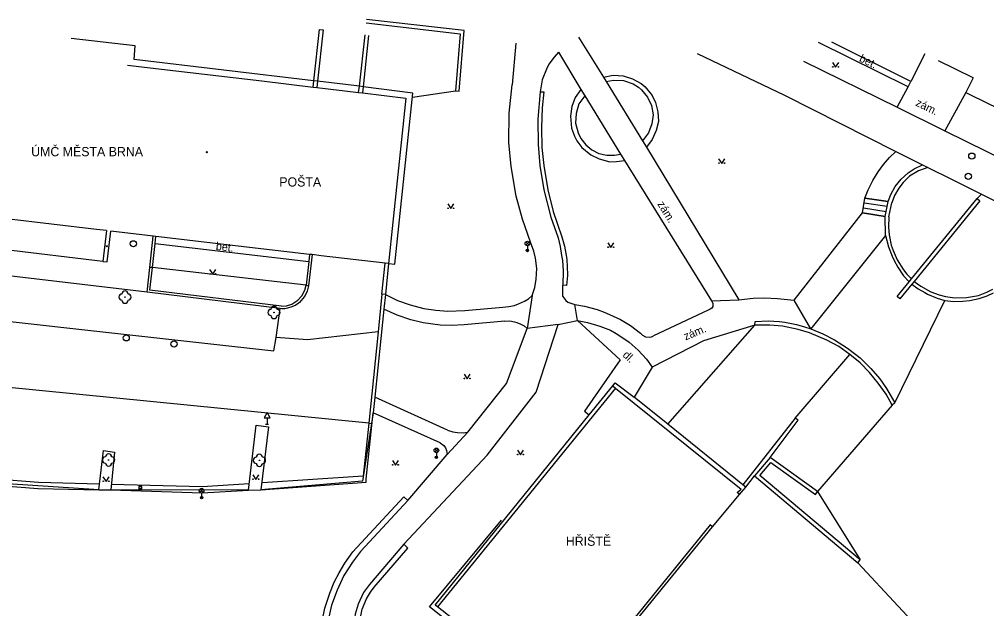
# Model space of a CAD drawing. Extents: x -602419 to -601554, y -1162937 to -1162362.
# Drawn here: x -602331.7 to -602253.1, y -1162453.4 to -1162405.5 of the extents above; entities that cross this region are included whole.
import ezdxf

# ---------------------------------------------------------------- set-up
doc = ezdxf.new("R2010")
doc.units = 0
doc.layers.add('Podklad', color=7, linetype='Continuous')

msp = doc.modelspace()

# ---------------------------------------------------------------- linework, layer by layer
at = {"layer": 'Podklad'}
for p, q in [((-602290.5725, -1162423.83), (-602290.3075, -1162423.565)), ((-602290.5725, -1162423.565), (-602290.3075, -1162423.83)), ((-602290.44, -1162423.885), (-602290.44, -1162424.26)), ((-602311.705, -1162438.36), (-602311.455, -1162438.36)), ((-602311.58, -1162437.851), (-602311.58, -1162438.36)), ((-602297.9625, -1162440.63), (-602297.6975, -1162440.365)), ((-602297.9625, -1162440.365), (-602297.6975, -1162440.63)), ((-602297.83, -1162440.685), (-602297.83, -1162441.06)), ((-602321.995, -1162443.56), (-602321.745, -1162443.56)), ((-602317.0325, -1162443.91), (-602316.7675, -1162443.645)), ((-602317.0325, -1162443.645), (-602316.7675, -1162443.91)), ((-602316.9, -1162443.965), (-602316.9, -1162444.34))]:
    msp.add_line(p, q, dxfattribs=at)
for points in [[(-602295.98, -1162411.33), (-602295.59, -1162406.4), (-602303.5, -1162405.49)], [(-602307.79, -1162410.49), (-602307.32, -1162406.31), (-602307.03, -1162406.35)], [(-602307.03, -1162406.35), (-602307.49, -1162410.52)], [(-602303.53, -1162405.78), (-602295.9099, -1162406.68), (-602296.27, -1162411.3), (-602295.98, -1162411.33)], [(-602307.8, -1162410.49), (-602322.39, -1162408.76), (-602322.3, -1162407.65), (-602327.48, -1162407.04)], [(-602304.09, -1162410.92), (-602303.63, -1162406.76)], [(-602303.34, -1162406.8), (-602303.79, -1162410.96)], [(-602286.3, -1162406.94), (-602284.26, -1162410.18)], [(-602291.38, -1162407.43), (-602291.68, -1162410.8)], [(-602259.53, -1162410.98), (-602266.8, -1162407.36)], [(-602259.3, -1162410.54), (-602265.73, -1162407.34)], [(-602287.9099, -1162408.1599), (-602288.26, -1162408.56), (-602288.7, -1162409.13), (-602288.9, -1162409.55), (-602289.24, -1162410.4), (-602289.4099, -1162411.39)], [(-602287.9099, -1162408.1599), (-602286.1, -1162411.19)], [(-602276.6599, -1162408.26), (-602269.55, -1162411.6599)], [(-602258.17, -1162408.3), (-602259.3, -1162410.54)], [(-602322.93, -1162409.2), (-602319, -1162409.67)], [(-602268.03, -1162408.89), (-602260.42, -1162412.63)], [(-602265.6599, -1162409.005), (-602265.4099, -1162409.38), (-602265.1599, -1162409.005)], [(-602254.25, -1162410.25), (-602257.06, -1162408.86)], [(-602319, -1162409.67), (-602312.02, -1162410.49)], [(-602284.26, -1162410.18), (-602283.4699, -1162410.03), (-602282.67, -1162410.07), (-602281.9099, -1162410.31), (-602281.2, -1162410.69), (-602280.89, -1162410.9699), (-602280.32, -1162411.67), (-602280.04, -1162412.25), (-602279.84, -1162413), (-602279.8, -1162413.78), (-602279.98, -1162414.53), (-602280.3, -1162415.24), (-602280.78, -1162415.86)], [(-602284.26, -1162410.18), (-602284.04, -1162410.54)], [(-602254.25, -1162410.25), (-602254.84, -1162411.42)], [(-602312.02, -1162410.49), (-602307.85, -1162410.99)], [(-602307.85, -1162410.99), (-602307.79, -1162410.49)], [(-602307.85, -1162410.99), (-602307.55, -1162411.02)], [(-602307.79, -1162410.49), (-602307.8, -1162410.49)], [(-602307.49, -1162410.52), (-602307.79, -1162410.49)], [(-602307.49, -1162410.52), (-602307.55, -1162411.02)], [(-602307.55, -1162411.02), (-602305.27, -1162411.3)], [(-602304.09, -1162410.92), (-602307.49, -1162410.52)], [(-602304.15, -1162411.43), (-602304.09, -1162410.92)], [(-602303.79, -1162410.96), (-602304.09, -1162410.92)], [(-602303.79, -1162410.96), (-602303.84, -1162411.4699)], [(-602301.73, -1162425.32), (-602301.21, -1162425.38), (-602299.74, -1162411.49), (-602303.79, -1162410.96)], [(-602290.05, -1162427.93), (-602289.85, -1162427.26), (-602289.74, -1162426.58), (-602289.68, -1162425.74), (-602289.78, -1162424.9), (-602289.9099, -1162424.32), (-602290.18, -1162423.58), (-602290.85, -1162421.73), (-602291.36, -1162419.84), (-602291.77, -1162417.43), (-602291.94, -1162415.49), (-602291.92, -1162413.11), (-602291.68, -1162410.8)], [(-602284.04, -1162410.54), (-602283.44, -1162410.42), (-602282.63, -1162410.46), (-602281.86, -1162410.7199), (-602281.42, -1162411.01), (-602281.18, -1162411.21), (-602280.7, -1162411.8), (-602280.37, -1162412.48), (-602280.24, -1162413.24), (-602280.35, -1162413.99), (-602280.61, -1162414.7), (-602281.09, -1162415.35)], [(-602284.04, -1162410.54), (-602281.09, -1162415.35)], [(-602260.42, -1162412.63), (-602259.53, -1162410.98)], [(-602259.53, -1162410.98), (-602259.3, -1162410.54)], [(-602305.27, -1162411.3), (-602304.15, -1162411.43)], [(-602304.15, -1162411.43), (-602303.84, -1162411.4699)], [(-602303.84, -1162411.4699), (-602300.32, -1162411.88)], [(-602300.32, -1162411.88), (-602301.73, -1162425.32)], [(-602299.7728, -1162411.7996), (-602296.27, -1162411.3)], [(-602289.4099, -1162411.39), (-602289.59, -1162413.6), (-602289.56, -1162415.6599), (-602289.42, -1162417.35), (-602289.1, -1162419.34), (-602288.53, -1162421.55), (-602287.94, -1162423.23), (-602287.77, -1162423.94), (-602287.6599, -1162424.6599), (-602287.59, -1162425.08), (-602287.53, -1162425.9099), (-602287.56, -1162427.07)], [(-602289.4099, -1162411.39), (-602289.11, -1162411.39)], [(-602289.11, -1162411.39), (-602289.24, -1162412.67), (-602289.3, -1162414.28), (-602289.26, -1162415.9), (-602289.11, -1162417.37), (-602288.79, -1162419.34), (-602288.34, -1162421.1), (-602287.64, -1162423.1599), (-602287.42, -1162423.92), (-602287.27, -1162424.81), (-602287.25, -1162425.04), (-602287.2, -1162425.54), (-602287.19, -1162426.3), (-602287.26, -1162427.1)], [(-602286.1, -1162411.19), (-602286.56, -1162411.83), (-602286.84, -1162412.57), (-602286.95, -1162413.35), (-602286.85, -1162414.33), (-602286.62, -1162414.98), (-602286.42, -1162415.35), (-602286.01, -1162415.89), (-602285.29, -1162416.49), (-602284.62, -1162416.83), (-602283.76, -1162417.05), (-602283.21, -1162417.03), (-602282.56, -1162416.95)], [(-602285.79, -1162411.7), (-602286.26, -1162412.36), (-602286.48, -1162413.13), (-602286.53, -1162413.93), (-602286.32, -1162414.71), (-602286.11, -1162415.1599), (-602285.71, -1162415.67), (-602285.21, -1162416.08), (-602284.63, -1162416.38), (-602284, -1162416.53), (-602283.36, -1162416.53), (-602282.87, -1162416.44)], [(-602286.1, -1162411.19), (-602285.79, -1162411.7)], [(-602285.79, -1162411.7), (-602282.87, -1162416.44)], [(-602269.55, -1162411.6599), (-602260.51, -1162416.2199)], [(-602254.84, -1162411.42), (-602256.53, -1162414.54)], [(-602254.84, -1162411.42), (-602254.45, -1162411.61)], [(-602254.45, -1162411.61), (-602252.12, -1162412.76)], [(-602260.42, -1162412.63), (-602256.53, -1162414.54)], [(-602256.53, -1162414.54), (-602248.07, -1162418.7199)], [(-602281.09, -1162415.35), (-602280.78, -1162415.86)], [(-602282.87, -1162416.44), (-602282.56, -1162416.95)], [(-602280.78, -1162415.86), (-602273.27, -1162428.26)], [(-602263.03, -1162420.01), (-602262.76, -1162419.34), (-602262.39, -1162418.57), (-602261.96, -1162417.87), (-602261.52, -1162417.27), (-602261.03, -1162416.7199), (-602260.51, -1162416.2199)], [(-602260.51, -1162416.2199), (-602258.36, -1162417.3)], [(-602282.56, -1162416.95), (-602275.5, -1162428.36)], [(-602274.9099, -1162416.815), (-602274.6599, -1162417.19), (-602274.4099, -1162416.815)], [(-602261.15, -1162420.29), (-602260.94, -1162419.71), (-602260.58, -1162419.07), (-602260.1, -1162418.4699), (-602259.53, -1162417.96), (-602259.03, -1162417.62), (-602258.36, -1162417.3)], [(-602258.36, -1162417.3), (-602257.9099, -1162417.52)], [(-602257.9099, -1162417.52), (-602258.69, -1162417.8), (-602259.4, -1162418.23), (-602259.93, -1162418.75), (-602260.29, -1162419.19), (-602260.63, -1162419.8), (-602260.86, -1162420.4)], [(-602257.9099, -1162417.52), (-602255.95, -1162418.51)], [(-602255.95, -1162418.51), (-602248.1599, -1162422.39)], [(-602253.92, -1162420.05), (-602253.5722, -1162419.6943)], [(-602296.9099, -1162420.485), (-602296.6599, -1162420.86), (-602296.4099, -1162420.485)], [(-602268.78, -1162428.31), (-602263.2199, -1162421.21), (-602263.03, -1162420.01)], [(-602261.23, -1162420.69), (-602263.09, -1162420.4099)], [(-602261.15, -1162420.29), (-602263.03, -1162420.01)], [(-602263.03, -1162420.01), (-602261.15, -1162420.29)], [(-602261.35, -1162423.06), (-602261.38, -1162421.49), (-602261.15, -1162420.29)], [(-602261.08, -1162421.52), (-602260.86, -1162420.4)], [(-602259.24, -1162426.57), (-602253.92, -1162420.05)], [(-602253.69, -1162420.24), (-602259.03, -1162426.77)], [(-602253.92, -1162420.05), (-602253.69, -1162420.24)], [(-602263.2199, -1162421.21), (-602261.38, -1162421.49)], [(-602261.38, -1162421.49), (-602263.2199, -1162421.21)], [(-602263.1599, -1162420.81), (-602261.31, -1162421.09)], [(-602325.43, -1162422.56), (-602332.74, -1162421.69)], [(-602261.08, -1162421.52), (-602261.11, -1162422.36), (-602261.06, -1162422.98), (-602260.89, -1162423.83), (-602260.75, -1162424.26), (-602260.42, -1162425.01), (-602259.9099, -1162425.83), (-602259.63, -1162426.18), (-602259.24, -1162426.57)], [(-602324.63, -1162422.65), (-602325.43, -1162422.56)], [(-602324.63, -1162422.65), (-602324.93, -1162425.15)], [(-602324.56, -1162425.19), (-602324.26, -1162422.7)], [(-602320.84, -1162423.09), (-602324.26, -1162422.7)], [(-602382.68, -1162423.5199), (-602382.868, -1162424.418), (-602311.04, -1162432.4129), (-602310.854, -1162431.328)], [(-602310.39, -1162429), (-602310.52, -1162428.98), (-602321.32, -1162427.65), (-602321.11, -1162425.65), (-602320.84, -1162423.09)], [(-602320.62, -1162423.12), (-602320.84, -1162423.09)], [(-602320.68, -1162423.69), (-602320.62, -1162423.12)], [(-602313.93, -1162423.9), (-602320.62, -1162423.12)], [(-602283.9099, -1162423.645), (-602283.6599, -1162424.02), (-602283.4099, -1162423.645)], [(-602261.35, -1162423.06), (-602267.42, -1162430.64)], [(-602261.35, -1162423.06), (-602261.12, -1162423.98), (-602260.83, -1162424.73), (-602260.6599, -1162425.07), (-602260.37, -1162425.61), (-602259.89, -1162426.32), (-602259.45, -1162426.82)], [(-602324.93, -1162425.15), (-602333.02, -1162424.18)], [(-602321.1, -1162427.48), (-602320.9, -1162425.65), (-602320.68, -1162423.69)], [(-602320.68, -1162423.69), (-602308.2, -1162425.15)], [(-602308.13, -1162424.58), (-602313.93, -1162423.9)], [(-602324.93, -1162425.15), (-602324.56, -1162425.19)], [(-602308.2, -1162425.15), (-602308.42, -1162427.08)], [(-602307.93, -1162424.6), (-602308.23, -1162427.14)], [(-602308.13, -1162424.58), (-602308.2, -1162425.15)], [(-602307.93, -1162424.6), (-602308.13, -1162424.58)], [(-602307.19, -1162424.69), (-602307.93, -1162424.6)], [(-602302, -1162425.29), (-602307.19, -1162424.69)], [(-602321.32, -1162427.65), (-602337.18, -1162425.77)], [(-602308.42, -1162427.08), (-602320.9, -1162425.65), (-602321.11, -1162425.65)], [(-602316.25, -1162425.815), (-602316, -1162426.19), (-602315.75, -1162425.815)], [(-602301.9699, -1162427.85), (-602302.27, -1162427.82), (-602302, -1162425.29)], [(-602301.73, -1162425.32), (-602302, -1162425.29)], [(-602301.73, -1162425.32), (-602301.9699, -1162427.85)], [(-602259.45, -1162426.82), (-602259.24, -1162426.57)], [(-602259.03, -1162426.77), (-602259.2199, -1162427.01)], [(-602259.03, -1162426.77), (-602258.5, -1162427.1599), (-602257.69, -1162427.63), (-602257, -1162427.87), (-602256.49, -1162428.01), (-602255.73, -1162428.11), (-602254.77, -1162428.09), (-602253.82, -1162427.9099), (-602253.13, -1162427.6599), (-602252.64, -1162427.4)], [(-602310.4099, -1162428.79), (-602321.1, -1162427.48)], [(-602310.4099, -1162428.79), (-602310, -1162428.76), (-602309.57, -1162428.62), (-602309.09, -1162428.31), (-602308.75, -1162427.94), (-602308.52, -1162427.5), (-602308.42, -1162427.08)], [(-602308.23, -1162427.14), (-602308.32, -1162427.56), (-602308.5, -1162427.92), (-602308.67, -1162428.1599), (-602308.96, -1162428.48), (-602309.25, -1162428.7), (-602309.58, -1162428.85), (-602309.93, -1162428.95), (-602310.14, -1162428.99), (-602310.39, -1162429)], [(-602308.42, -1162427.08), (-602308.23, -1162427.14)], [(-602287.57, -1162428), (-602287.56, -1162427.07)], [(-602287.26, -1162427.1), (-602287.56, -1162427.07)], [(-602259.2199, -1162427.01), (-602260.19, -1162428.2), (-602260.42, -1162428.01), (-602259.45, -1162426.82)], [(-602259.2199, -1162427.01), (-602258.71, -1162427.37), (-602258.17, -1162427.68), (-602257.94, -1162427.8), (-602257.1599, -1162428.14), (-602256.53, -1162428.32)], [(-602302.2699, -1162427.82), (-602302.56, -1162430.8799)], [(-602301.9699, -1162427.85), (-602302.09, -1162429.04)], [(-602301.9699, -1162427.85), (-602300.99, -1162428.32), (-602299.9699, -1162428.68), (-602298.84, -1162428.9699), (-602297.88, -1162429.11), (-602296.9099, -1162429.2), (-602295.52, -1162429.15)], [(-602292.44, -1162428.86), (-602291.95, -1162428.82), (-602291.48, -1162428.7199), (-602291.1599, -1162428.6), (-602290.69, -1162428.38), (-602290.35, -1162428.18), (-602290.05, -1162427.93)], [(-602290.05, -1162427.93), (-602290.46, -1162430.59)], [(-602287.57, -1162428), (-602287.31, -1162428.32), (-602287.17, -1162428.45), (-602286.6, -1162428.65), (-602285.81, -1162428.79), (-602284.79, -1162429.05), (-602284.2, -1162429.27), (-602283.77, -1162429.45), (-602282.89, -1162429.87), (-602282.06, -1162430.37), (-602281.26, -1162430.98)], [(-602275.5, -1162428.36), (-602275.39, -1162428.53), (-602275.37, -1162428.7), (-602275.39, -1162428.81), (-602275.4699, -1162428.94), (-602275.59, -1162429.04), (-602275.75, -1162429.11)], [(-602275.5, -1162428.36), (-602273.27, -1162428.26)], [(-602273.27, -1162428.26), (-602272.1, -1162428.14), (-602271.2, -1162428.12), (-602270.12, -1162428.1599), (-602268.78, -1162428.31)], [(-602267.42, -1162430.64), (-602268.78, -1162428.31)], [(-602260.59, -1162436.65), (-602256.53, -1162428.32)], [(-602256.53, -1162428.32), (-602255.81, -1162428.4), (-602255.08, -1162428.39), (-602254.51, -1162428.32), (-602253.75, -1162428.17), (-602253.11, -1162427.95), (-602252.59, -1162427.7)], [(-602310.85, -1162431.33), (-602310.52, -1162428.98)], [(-602302.09, -1162429.04), (-602302.84, -1162436.19)], [(-602295.58, -1162430.31), (-602296.63, -1162430.36), (-602297.52, -1162430.32), (-602298.92, -1162430.13), (-602299.9099, -1162429.9), (-602301.03, -1162429.53), (-602302.09, -1162429.04)], [(-602295.52, -1162429.15), (-602292.44, -1162428.86)], [(-602286.37, -1162429.96), (-602286.6, -1162428.65)], [(-602275.75, -1162429.11), (-602280.19, -1162431.2)], [(-602390.76, -1162429.6299), (-602390.9, -1162429.8299), (-602390.9383, -1162429.8874), (-602391.04, -1162430.0399), (-602388.52, -1162431.7799), (-602387.3183, -1162432.2378), (-602383.56, -1162433.67), (-602379.14, -1162435.1299), (-602366.94, -1162438.5199), (-602355.37, -1162440.8099), (-602342.01, -1162442.67), (-602330.16, -1162443.6), (-602325.25, -1162443.7), (-602324.28, -1162443.71), (-602316.85, -1162443.9599), (-602313.1, -1162443.73), (-602312.1, -1162443.7), (-602303.53, -1162443.0799), (-602303.54, -1162442.8299), (-602302.98, -1162437.45)], [(-602303.326, -1162438.2979), (-602383.3931, -1162430.3601), (-602383.5311, -1162430.3467), (-602384.2262, -1162430.2776)], [(-602300.48, -1162448.13), (-602293.71, -1162440.9), (-602289.74, -1162435.78), (-602287.94, -1162430.28), (-602286.37, -1162429.96)], [(-602292.28, -1162430.01), (-602295.58, -1162430.31)], [(-602295.29, -1162439.01), (-602292.15, -1162435.08), (-602290.46, -1162430.59)], [(-602292.28, -1162430.01), (-602291.88, -1162429.99), (-602291.48, -1162430.05), (-602291.31, -1162430.1), (-602290.9699, -1162430.24), (-602290.7, -1162430.39), (-602290.46, -1162430.59)], [(-602287.94, -1162430.28), (-602290.46, -1162430.59)], [(-602286.37, -1162429.96), (-602282.92, -1162433.14), (-602285.8, -1162437.31), (-602285.42, -1162437.62)], [(-602286.37, -1162429.96), (-602285.55, -1162430.12), (-602284.57, -1162430.4), (-602283.69, -1162430.74), (-602283.23, -1162431.01), (-602282.93, -1162431.19), (-602282.19, -1162431.71), (-602281.45, -1162432.36), (-602280.78, -1162433.1), (-602280.32, -1162433.74)], [(-602271.9699, -1162430.33), (-602276.13, -1162431.61), (-602280.32, -1162433.74)], [(-602279.04, -1162438.38), (-602271.97, -1162430.33)], [(-602271.9699, -1162430.33), (-602271.95, -1162430.03)], [(-602260.83, -1162436.83), (-602261.32, -1162435.94), (-602261.95, -1162435.03), (-602262.6599, -1162434.17), (-602263.43, -1162433.4), (-602264.27, -1162432.7), (-602265.1599, -1162432.06), (-602266.13, -1162431.54), (-602267.52, -1162430.94), (-602268.46, -1162430.67), (-602269.7199, -1162430.42), (-602270.75, -1162430.32), (-602271.9699, -1162430.33)], [(-602271.95, -1162430.03), (-602270.89, -1162429.98), (-602269.9699, -1162430.03), (-602269.53, -1162430.09), (-602268.6, -1162430.27), (-602267.93, -1162430.46), (-602267.42, -1162430.64)], [(-602267.42, -1162430.64), (-602266.44, -1162431.03), (-602265.51, -1162431.51), (-602264.45, -1162432.19), (-602263.76, -1162432.7), (-602263.43, -1162432.99), (-602262.54, -1162433.85), (-602261.83, -1162434.69), (-602261.27, -1162435.4699), (-602260.59, -1162436.65)], [(-602302.56, -1162430.8799), (-602308.31, -1162431.5299), (-602310.854, -1162431.328)], [(-602302.56, -1162430.8799), (-602303.326, -1162438.2979)], [(-602281.26, -1162430.98), (-602281.09, -1162431.14), (-602280.84, -1162431.28), (-602280.56, -1162431.31), (-602280.36, -1162431.28), (-602280.19, -1162431.2)], [(-602268.7, -1162437.87), (-602264.27, -1162432.7)], [(-602280.32, -1162433.74), (-602281.77, -1162436.18)], [(-602295.58, -1162434.315), (-602295.33, -1162434.69), (-602295.08, -1162434.315)], [(-602283.28, -1162435.44), (-602297.75, -1162453.21)], [(-602285.42, -1162437.62), (-602283.51, -1162435.26)], [(-602283.51, -1162435.26), (-602283.31, -1162435.01)], [(-602283.51, -1162435.26), (-602283.28, -1162435.44)], [(-602283.31, -1162435.01), (-602281.77, -1162436.18)], [(-602283.28, -1162435.44), (-602273.09, -1162443.64)], [(-602302.84, -1162436.19), (-602302.98, -1162437.45)], [(-602296.93, -1162438.87), (-602302.84, -1162436.19)], [(-602272.94, -1162443.29), (-602279.04, -1162438.38), (-602281.77, -1162436.18)], [(-602260.83, -1162436.83), (-602266.87, -1162443.83)], [(-602260.59, -1162436.65), (-602260.83, -1162436.83)], [(-602302.98, -1162437.45), (-602303.11, -1162438.31), (-602303.83, -1162443.01), (-602312.1, -1162443.7)], [(-602297.52, -1162439.88), (-602302.98, -1162437.45)], [(-602297.93, -1162453.07), (-602285.42, -1162437.62)], [(-602313.1, -1162443.73), (-602312.4699, -1162438.46), (-602311.48, -1162438.59), (-602312.1, -1162443.7)], [(-602303.326, -1162438.2979), (-602303.77, -1162442.5899), (-602311.96, -1162443.1299), (-602312.0314, -1162443.1346)], [(-602303.33, -1162438.3), (-602303.11, -1162438.31)], [(-602268.7, -1162437.87), (-602272.94, -1162443.29)], [(-602270.7199, -1162441.08), (-602268.46, -1162438.05)], [(-602268.46, -1162438.05), (-602268.7, -1162437.87)], [(-602296.95, -1162440.84), (-602295.29, -1162439.01)], [(-602296.93, -1162438.87), (-602296.51, -1162439), (-602296.12, -1162439.05), (-602295.65, -1162439.07), (-602295.29, -1162439.01)], [(-602297.52, -1162439.88), (-602297.23, -1162440.1), (-602297.1, -1162440.3), (-602297, -1162440.52), (-602296.95, -1162440.84)], [(-602325.25, -1162443.7), (-602324.87, -1162440.52), (-602323.9699, -1162440.65), (-602324.28, -1162443.71)], [(-602300.1599, -1162444.58), (-602296.95, -1162440.84)], [(-602291.25, -1162440.485), (-602291, -1162440.86), (-602290.75, -1162440.485)], [(-602301.4099, -1162441.325), (-602301.1599, -1162441.7), (-602300.9099, -1162441.325)], [(-602270.7199, -1162441.08), (-602272, -1162442.58)], [(-602263.42, -1162449.39), (-602271.58, -1162442.54), (-602270.67, -1162441.49), (-602267.04, -1162444.07), (-602266.87, -1162443.83)], [(-602266.87, -1162443.83), (-602270.7199, -1162441.08)], [(-602312.75, -1162442.485), (-602312.5, -1162442.86), (-602312.25, -1162442.485)], [(-602325.25, -1162443.7), (-602336.4, -1162442.96)], [(-602325.1945, -1162443.2354), (-602330.14, -1162443.1), (-602336.3714, -1162442.6123)], [(-602324.9099, -1162442.655), (-602324.6599, -1162443.03), (-602324.4099, -1162442.655)], [(-602313.0376, -1162443.2082), (-602316.86, -1162443.4599), (-602324.2344, -1162443.2596)], [(-602272.7, -1162443.49), (-602272.94, -1162443.29)], [(-602272.7, -1162443.49), (-602272, -1162442.58)], [(-602272, -1162442.58), (-602263.62, -1162449.62)], [(-602313.1, -1162443.73), (-602324.28, -1162443.71)], [(-602275.42, -1162446.71), (-602273.21, -1162444.09)], [(-602273.4, -1162443.93), (-602273.09, -1162443.64)], [(-602273.21, -1162444.09), (-602273.4, -1162443.93)], [(-602273.21, -1162444.09), (-602272.7, -1162443.49)], [(-602266.87, -1162443.83), (-602263.42, -1162449.39)], [(-602300.1599, -1162444.58), (-602300.48, -1162444.28), (-602303.6, -1162447.64)], [(-602303.26, -1162447.93), (-602300.1599, -1162444.58)], [(-602288.05, -1162461.4699), (-602298.39, -1162453.21), (-602292.54, -1162446.17)], [(-602275.42, -1162446.71), (-602275.61, -1162446.55), (-602286.03, -1162459.37), (-602285.85, -1162459.51)], [(-602282.81, -1162455.78), (-602275.42, -1162446.71)], [(-602307.1, -1162454.37), (-602306.89, -1162453.32), (-602306.5, -1162452.11), (-602306.13, -1162451.19), (-602305.74, -1162450.45), (-602305.27, -1162449.65), (-602304.61, -1162448.75), (-602303.6, -1162447.64)], [(-602303.26, -1162447.93), (-602303.99, -1162448.7199), (-602304.64, -1162449.57), (-602305.34, -1162450.67), (-602305.9, -1162451.85), (-602306.34, -1162453.08), (-602306.67, -1162454.52)], [(-602300.48, -1162448.13), (-602303.27, -1162451.38)], [(-602302.88, -1162451.62), (-602300.14, -1162448.43), (-602300.48, -1162448.13)], [(-602263.62, -1162449.62), (-602263.42, -1162449.39)], [(-602263.62, -1162449.62), (-602257.05, -1162456.68), (-602259.1, -1162459.22), (-602267.1, -1162469.1), (-602281.85, -1162456.59)], [(-602303.27, -1162451.38), (-602303.75, -1162452.04), (-602304.19, -1162452.99), (-602304.43, -1162453.79), (-602304.53, -1162454.67), (-602304.5, -1162455.55), (-602304.23, -1162456.74), (-602303.83, -1162457.6), (-602303.27, -1162458.36), (-602302.75, -1162458.87), (-602302.17, -1162459.36), (-602301.4, -1162459.89), (-602300.51, -1162460.27)], [(-602300.36, -1162459.84), (-602300.95, -1162459.57), (-602301.53, -1162459.26), (-602302.08, -1162458.85), (-602302.6, -1162458.4), (-602303.05, -1162457.89), (-602303.42, -1162457.38), (-602303.6599, -1162456.9), (-602303.89, -1162456.25), (-602304.03, -1162455.58), (-602304.06, -1162454.7), (-602304, -1162454.06), (-602303.85, -1162453.39), (-602303.51, -1162452.56), (-602303.19, -1162452.02), (-602302.88, -1162451.62)], [(-602297.75, -1162453.21), (-602297.93, -1162453.07)], [(-602287.53, -1162461.24), (-602297.75, -1162453.21)]]:
    msp.add_lwpolyline(points, dxfattribs=at)
for points in [[(-602311.83, -1162437.851), (-602311.33, -1162437.851), (-602311.58, -1162437.418)], [(-602321.995, -1162443.685), (-602321.745, -1162443.685), (-602321.745, -1162443.435), (-602321.995, -1162443.435)]]:
    msp.add_lwpolyline(points, close=True, dxfattribs=at)
for centre, radius in [((-602265.635, -1162409.3549), 0.025), ((-602265.1853, -1162409.3549), 0.025), ((-602316.48, -1162416.28), 0.045), ((-602316.48, -1162416.28), 0.0199), ((-602254.35, -1162416.6), 0.25), ((-602274.885, -1162417.1649), 0.025), ((-602274.4353, -1162417.1649), 0.025), ((-602254.64, -1162418.24), 0.25), ((-602296.885, -1162420.8349), 0.025), ((-602296.4353, -1162420.8349), 0.025), ((-602322.44, -1162423.7199), 0.25), ((-602290.44, -1162423.6975), 0.1875), ((-602324.59, -1162423.92), 0.045), ((-602324.59, -1162423.92), 0.0199), ((-602290.44, -1162424.26), 0.1), ((-602290.44, -1162424.26), 0.0723), ((-602290.44, -1162424.26), 0.0438), ((-602283.885, -1162423.9949), 0.025), ((-602283.4353, -1162423.9949), 0.025), ((-602316.2251, -1162426.1649), 0.025), ((-602315.7754, -1162426.1649), 0.025), ((-602323.12, -1162428.05), 0.025), ((-602311.02, -1162429.3), 0.025), ((-602323.02, -1162431.36), 0.25), ((-602319.14, -1162431.86), 0.25), ((-602295.5551, -1162434.6649), 0.025), ((-602295.1054, -1162434.6649), 0.025), ((-602297.83, -1162440.4975), 0.1875), ((-602291.2251, -1162440.8349), 0.025), ((-602290.7754, -1162440.8349), 0.025), ((-602324.46, -1162441.28), 0.025), ((-602312.2, -1162441.31), 0.025), ((-602301.385, -1162441.6749), 0.025), ((-602300.9353, -1162441.6749), 0.025), ((-602297.83, -1162441.06), 0.1), ((-602297.83, -1162441.06), 0.0723), ((-602297.83, -1162441.06), 0.0438), ((-602324.885, -1162443.0049), 0.025), ((-602324.4353, -1162443.0049), 0.025), ((-602312.7251, -1162442.8349), 0.025), ((-602312.2754, -1162442.8349), 0.025), ((-602316.9, -1162443.7775), 0.1875), ((-602316.9, -1162444.34), 0.1), ((-602316.9, -1162444.34), 0.0723), ((-602316.9, -1162444.34), 0.0438)]:
    msp.add_circle(centre, radius, dxfattribs=at)
for centre, start, end in [((-602323.12, -1162427.8), 0, 180), ((-602323.37, -1162428.05), 90, 270), ((-602323.12, -1162428.3), 180, 0), ((-602322.87, -1162428.05), 270, 90), ((-602311.27, -1162429.3), 90, 270), ((-602311.02, -1162429.05), 0, 180), ((-602310.77, -1162429.3), 270, 90), ((-602311.02, -1162429.55), 180, 0), ((-602324.46, -1162441.03), 0, 180), ((-602312.2, -1162441.06), 0, 180), ((-602324.71, -1162441.28), 90, 270), ((-602324.46, -1162441.53), 180, 0), ((-602324.21, -1162441.28), 270, 90), ((-602312.45, -1162441.31), 90, 270), ((-602312.2, -1162441.56), 180, 0), ((-602311.95, -1162441.31), 270, 90)]:
    msp.add_arc(centre, 0.25, start, end, dxfattribs=at)

# ---------------------------------------------------------------- texts
for s, rotation, p in [('bet.', 333.89, (-602263.55, -1162408.87)), (' zám.', 333.89, (-602259.19, -1162412.37)), (' zám.', 301.52, (-602280.04, -1162420.28)), ('bet.', 353.17, (-602315.77, -1162424.21)), (' zám.', 22.21, (-602277.82, -1162431.6599)), ('dl.', 317.33, (-602282.76, -1162432.82))]:
    msp.add_text(s, height=0.65, rotation=rotation, dxfattribs=at).set_placement(p)
for s, p in [('ÚMČ MĚSTA BRNA', (-602330.74, -1162416.61)), ('POŠTA', (-602310.59, -1162419.07)), ('HŘIŠTĚ', (-602287.32, -1162448.25))]:
    msp.add_text(s, height=0.75, dxfattribs=at).set_placement(p)

doc.saveas('drawing.dxf')
